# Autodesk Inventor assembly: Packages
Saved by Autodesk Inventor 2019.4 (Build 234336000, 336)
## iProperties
Created: 2021-02
Part Number: Packages
Document SubType Name: Assembly
Designer: Administrator
Title: Packages
Author: Administrator
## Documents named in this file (18)
- c:\worker\convert-fusion-r01\tmp\job-1\28\output\files\da425021-f5ae-4251-bf5a-5edd51761a99\Packages.iam
- c:\worker\convert-fusion-r01\tmp\job-1\28\output\files\da425021-f5ae-4251-bf5a-5edd51761a99\SOIC127P600X175-8N.ipt
- c:\worker\convert-fusion-r01\tmp\job-1\28\output\files\da425021-f5ae-4251-bf5a-5edd51761a99\SOP28P65_970X640X120L60X24T483X275N.ipt
- c:\worker\convert-fusion-r01\tmp\job-1\28\output\files\da425021-f5ae-4251-bf5a-5edd51761a99\JST_SM03B-SRSS-TB(LF)(SN).ipt
- c:\worker\convert-fusion-r01\tmp\job-1\28\output\files\da425021-f5ae-4251-bf5a-5edd51761a99\JST_SM04B-SRSS-TB(LF)(SN).ipt
- c:\worker\convert-fusion-r01\tmp\job-1\28\output\files\da425021-f5ae-4251-bf5a-5edd51761a99\SM06B.ipt
- c:\worker\convert-fusion-r01\tmp\job-1\28\output\files\da425021-f5ae-4251-bf5a-5edd51761a99\0402.ipt
- c:\worker\convert-fusion-r01\tmp\job-1\28\output\files\da425021-f5ae-4251-bf5a-5edd51761a99\0603.ipt
- c:\worker\convert-fusion-r01\tmp\job-1\28\output\files\da425021-f5ae-4251-bf5a-5edd51761a99\LED-0603.ipt
- c:\worker\convert-fusion-r01\tmp\job-1\28\output\files\da425021-f5ae-4251-bf5a-5edd51761a99\0603 (1).ipt
- c:\worker\convert-fusion-r01\tmp\job-1\28\output\files\da425021-f5ae-4251-bf5a-5edd51761a99\TACTILE_SWITCH_SMD_RIGHT_ANGLE.ipt
- c:\worker\convert-fusion-r01\tmp\job-1\28\output\files\da425021-f5ae-4251-bf5a-5edd51761a99\0603-CAP.ipt
- c:\worker\convert-fusion-r01\tmp\job-1\28\output\files\da425021-f5ae-4251-bf5a-5edd51761a99\0603-RES.ipt
- c:\worker\convert-fusion-r01\tmp\job-1\28\output\files\da425021-f5ae-4251-bf5a-5edd51761a99\TQFP32-08.ipt
- c:\worker\convert-fusion-r01\tmp\job-1\28\output\files\da425021-f5ae-4251-bf5a-5edd51761a99\CON4_1X4_DRB2_MOL.ipt
- c:\worker\convert-fusion-r01\tmp\job-1\28\output\files\da425021-f5ae-4251-bf5a-5edd51761a99\RESONATOR_MURATA2.ipt
- c:\worker\convert-fusion-r01\tmp\job-1\28\output\files\da425021-f5ae-4251-bf5a-5edd51761a99\C1206.ipt
- c:\worker\convert-fusion-r01\tmp\job-1\28\output\files\da425021-f5ae-4251-bf5a-5edd51761a99\R0603.ipt
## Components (27 placed, 27 different names)
1. SOIC127P600X175-8N:IC1
2. SOP28P65_970X640X120L60X24T483X275N:U1
3. JST_SM03B-SRSS-TB(LF)(SN):MOT
4. JST_SM03B-SRSS-TB(LF)(SN):5V
5. JST_SM04B-SRSS-TB(LF)(SN):PRO
6. JST_SM04B-SRSS-TB(LF)(SN):PWR
7. SM06B:NEFI
8. 0402:C8
9. 0402:C9
10. 0603:C3
11. 0603:C4
12. 0603:C5
13. LED-0603:D1
14. 0603 (1):R1
15. TACTILE_SWITCH_SMD_RIGHT_ANGLE:S2
16. 0603-CAP:C1
17. 0603-CAP:C11
18. 0603-CAP:C2
19. 0603-RES:R2
20. 0603-RES:R3
21. 0603-RES:R8
22. 0603-RES:R5
23. TQFP32-08:U3
24. CON4_1X4_DRB2_MOL:EN_EXT
25. RESONATOR_MURATA2:Q2
26. C1206:C15
27. R0603:R4
